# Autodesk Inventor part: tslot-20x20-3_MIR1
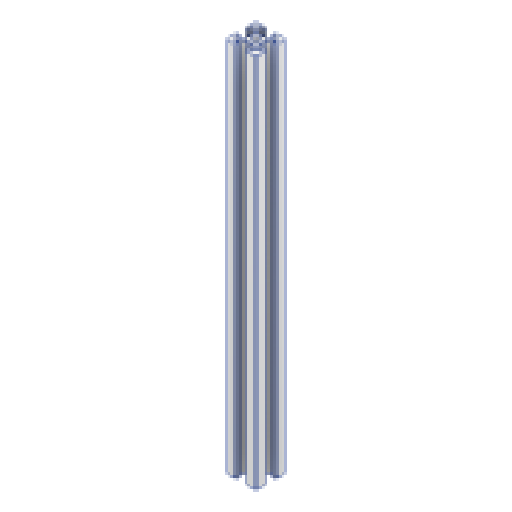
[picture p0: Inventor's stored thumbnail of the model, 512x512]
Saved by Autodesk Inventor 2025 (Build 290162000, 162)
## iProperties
Created: 2025-03
Part Number: tslot-20x20-3_MIR1
Material: Alluminio 6061
Document SubType Name: Modeling
Designer: Ryzen5700u
Density: 2.7 g/cm^3
Appearance: Alluminio - Piatto
Author: Ryzen5700u
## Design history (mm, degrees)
derived "tslot-20x20-3.ipt"
  sketch "Schizzo1"
    geometry: L1 (-3.761, -16)-(-4.7, -16) reference; L2 (-3.761, -16)-(-0.7, -12.939) reference; L3 (-0.7, -12.939)-(-0.7, -10.52) reference; L4 (-0.4, -10)-(-0.7, -10.52) reference; L5 (-0.4, -10)-(-0.7, -9.48) reference; L6 (-0.7, -7.061)-(-0.7, -9.48) reference; L7 (-3.761, -4)-(-0.7, -7.061) reference; L8 (-3.761, -4)-(-4.7, -4) reference; L9 (-4.7, -4)-(-4.7, -7) reference; L10 (-4.7, -7)-(-6.4, -7) reference; L11 (-6.7, -6.7)-(-6.7, -1) reference; L12 (-5.7, 0)-(0, 0) reference; L13 (0.3, -2)-(0.3, -0.3) reference; L14 (-2.7, -2)-(0.3, -2) reference; L15 (-2.7, -2.939)-(-2.7, -2) reference; L16 (-2.7, -2.939)-(0.361, -6) reference; L17 (0.361, -6)-(2.78, -6) reference; L18 (3.3, -6.3)-(2.78, -6) reference; L19 (3.3, -6.3)-(3.82, -6) reference; L20 (6.239, -6)-(3.82, -6) reference; L21 (9.3, -2.939)-(6.239, -6) reference; L22 (9.3, -2.939)-(9.3, -2) reference; L23 (9.3, -2)-(6.3, -2) reference; L24 (6.3, -2)-(6.3, -0.3) reference; L25 (12.3, 0)-(6.6, 0) reference; L26 (13.3, -6.7)-(13.3, -1) reference; L27 (11.3, -7)-(13, -7) reference; L28 (11.3, -4)-(11.3, -7) reference; L29 (10.361, -4)-(11.3, -4) reference; L30 (10.361, -4)-(7.3, -7.061) reference; L31 (7.3, -7.061)-(7.3, -9.48) reference; L32 (7, -10)-(7.3, -9.48) reference; L33 (7, -10)-(7.3, -10.52) reference; L34 (7.3, -12.939)-(7.3, -10.52) reference; L35 (10.361, -16)-(7.3, -12.939) reference; L36 (10.361, -16)-(11.3, -16) reference; L37 (11.3, -16)-(11.3, -13) reference; L38 (11.3, -13)-(13, -13) reference; L39 (13.3, -13.3)-(13.3, -19) reference; L40 (12.3, -20)-(6.6, -20) reference; L41 (6.3, -18)-(6.3, -19.7) reference; L42 (9.3, -18)-(6.3, -18) reference; L43 (9.3, -17.061)-(9.3, -18) reference; L44 (9.3, -17.061)-(6.239, -14) reference; L45 (6.239, -14)-(3.82, -14) reference; L46 (3.3, -13.7)-(3.82, -14) reference; L47 (3.3, -13.7)-(2.78, -14) reference; L48 (0.361, -14)-(2.78, -14) reference; L49 (-2.7, -17.061)-(0.361, -14) reference; L50 (-2.7, -17.061)-(-2.7, -18) reference; L51 (-2.7, -18)-(0.3, -18) reference; L52 (0.3, -18)-(0.3, -19.7) reference; L53 (-5.7, -20)-(0, -20) reference; L54 (-6.7, -13.3)-(-6.7, -19) reference; L55 (-4.7, -13)-(-6.4, -13) reference; L56 (-4.7, -16)-(-4.7, -13) reference; C1 r 2.1 at (3.3, -10) reference; A1 r 0.3 centre (-6.4, -6.7) between (-6.7, -6.7) and (-6.4, -7) reference; A2 r 1 centre (-5.7, -1) between (-5.7, 0) and (-6.7, -1) reference; A3 r 0.3 centre (0, -0.3) between (0.3, -0.3) and (0, 0) reference; A4 r 0.3 centre (6.6, -0.3) between (6.6, 0) and (6.3, -0.3) reference; A5 r 1 centre (12.3, -1) between (13.3, -1) and (12.3, 0) reference; A6 r 0.3 centre (13, -6.7) between (13, -7) and (13.3, -6.7) reference; A7 r 0.3 centre (13, -13.3) between (13.3, -13.3) and (13, -13) reference; A8 r 1 centre (12.3, -19) between (12.3, -20) and (13.3, -19) reference; A9 r 0.3 centre (6.6, -19.7) between (6.3, -19.7) and (6.6, -20) reference; A10 r 0.3 centre (0, -19.7) between (0, -20) and (0.3, -19.7) reference; A11 r 1 centre (-5.7, -19) between (-6.7, -19) and (-5.7, -20) reference; A12 r 0.3 centre (-6.4, -13.3) between (-6.4, -13) and (-6.7, -13.3) reference; 1 further point
feature "Solido1::tslot-20x20-3.ipt" dims "d0" = 10
tag "Lavorazione contrassegno1"
node "Solido1"
